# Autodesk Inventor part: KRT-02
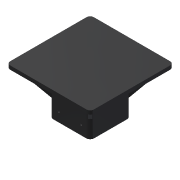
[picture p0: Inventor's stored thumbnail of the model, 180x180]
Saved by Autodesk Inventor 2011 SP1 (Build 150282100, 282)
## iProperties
Created: 2011-02
Part Number: KRT-02
Material: Rubber
Document SubType Name: Modeling
Designer: SERGIO
Mass: 856.468 g
Surface Area: 1984.01 cm^2
Volume: 920.933 cm^3
Density: 0.93 g/cm^3
Author: SERGIO
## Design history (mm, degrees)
sketch "Sketch1"
  geometry: L1 (-50, -44)-(-50, 44) reference; L2 (44, -50)-(-44, -50) reference; L3 (50, 44)-(50, -44) reference; L4 (-44, 50)-(44, 50) reference; L5 (-55, 44)-(-55, -44); L6 (-44, -55)-(44, -55); L7 (55, -44)-(55, 44); L8 (44, 55)-(-44, 55); A1 r 6 centre (-44, -44) between (-50, -44) and (-44, -50) reference; A2 r 6 centre (44, -44) between (44, -50) and (50, -44) reference; A3 r 6 centre (44, 44) between (50, 44) and (44, 50) reference; A4 r 6 centre (-44, 44) between (-44, 50) and (-50, 44) reference; A5 r 11 centre (-44, -44) between (-55, -44) and (-44, -55); A6 r 11 centre (44, -44) between (44, -55) and (55, -44); A7 r 11 centre (44, 44) between (55, 44) and (44, 55); A8 r 11 centre (-44, 44) between (-44, 55) and (-55, 44); 1 further point
  constraints: 16 end point, 16 point on circle, 8 centre point, 2 horizontal, 2 vertical, 23 other
  dimensions: "d0" = 5 distance between parallel lines of L1 L5
extrude "Extrusion1" new body sketch "Sketch1" distance "d1" = 15; taper "d3" = 0 deg; dims "d2" = 100, "d4" = 0
extrude "Extrusion2" join sketch "Sketch1" stored distance "d5" = 15; taper "d6" = 0 deg
sketch "Sketch2"
  geometry: L1 (-55, -44)-(-55, 44) reference; L2 (-44, 55)-(44, 55) reference; L3 (-112.5, -112.5)-(112.5, -112.5); L4 (112.5, -112.5)-(112.5, 112.5); L5 (112.5, 112.5)-(-112.5, 112.5); L6 (-112.5, 112.5)-(-112.5, -112.5); 6 further points
  constraints: 8 end point, 5 midpoint, 2 parallel, 1 horizontal, 1 horizontal alignment, 1 perpendicular, 1 vertical alignment
  dimensions: "d7" = 225 distance of L4.end L5.end; "d8" = 225 distance of L3.end L4.end
extrude "Extrusion3" join sketch "Sketch2" distance "d9" = 10; taper "d10" = 0 deg
workplane "Work Plane1"
workpoint "Work Point1"
workpoint "Work Point2"
workpoint "Work Point3"
sketch "Sketch3"
  geometry: L1 (-52.5, 73.225)-(15, 140.725); L2 (15, 0)-(15, 159.099) reference; 3 further points
  constraints: 2 end point, 1 horizontal alignment, 1 vertical alignment
  dimensions: "d12" = 45 deg angle of L2 L1; "d13" = 67.5 distance of point (15, 73.225) L1.start
feature "Rib1" sketch "Sketch3" dims "d14" = 1, "d15" = 8, "d16" = 0
fillet "Fillet1" dims "d17" = 10
pattern_circular "Circular Pattern1" dims angle "d19" = 360 deg
sketch "Sketch4"
  geometry: L1 (44, 138)-(44, -23) reference; L2 (88, 115)-(0, 115) reference; L3 (88, 0)-(88, 115) reference; C1 r 3 at (74, 75); C2 r 3 at (74, 25); C3 r 3 at (14, 75); C4 r 3 at (14, 25); 1 further point
  constraints: 4 centre point, 2 symmetric about line, 1 equal radius, 1 vertical alignment, 2 other
  dimensions: "d23" = 40 distance from line of L2 C1.centre; "d24" = 14 distance from line of L3 C1.centre; "d26" = 6 diameter of C1; "d27" = 50 distance of C2.centre C1.centre
extrude "Extrusion4" cut sketch "Sketch4" stored distance "d21" = 10; taper "d22" = 0 deg
body "Solid1"
other parameters: "d11" = 45 deg
